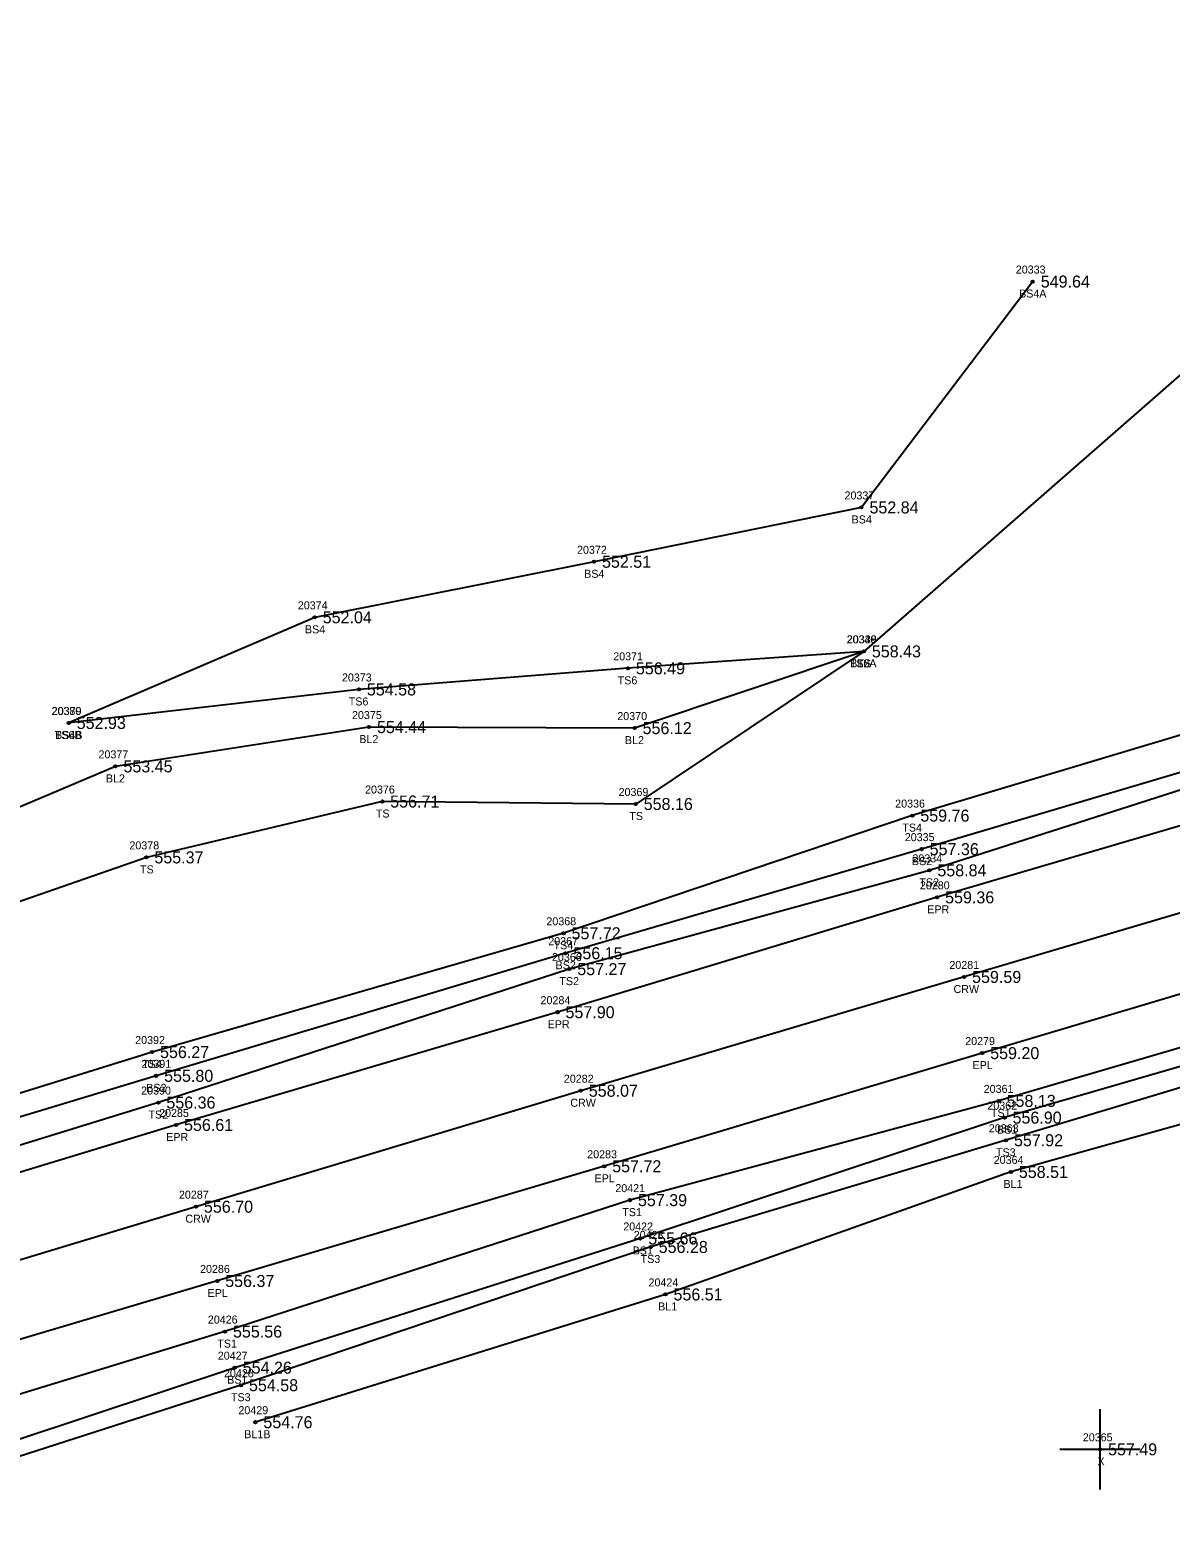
# Model space of a CAD drawing. Extents: x 1540443 to 1541844, y 887157 to 888162.
# Drawn here: x 1541511.2 to 1541653.6, y 887753.4 to 887940.4 of the extents above; entities that cross this region are included whole.
import ezdxf

# ---------------------------------------------------------------- set-up
doc = ezdxf.new("R2010")
doc.units = 0
for name, color, linetype in [('RD_DTM_BkLn1', 7, 'Continuous'), ('RD_DTM_BkLn2', 7, 'Continuous'), ('RD_DTM_BkLn_txCode', 7, 'Continuous'), ('RD_EX_Misc', 7, 'Continuous'), ('RD_EX_Misc_txCode', 7, 'Continuous'), ('RD_EX_Road', 7, 'Continuous'), ('RD_EX_Road_txCode', 7, 'Continuous'), ('RD_EX_TX_Misc_ELEV', 7, 'Continuous'), ('RD_EX_TX_Road_ELEV', 7, 'Continuous'), ('RD_HC_Survey_ELEV', 7, 'Continuous'), ('RD_HC_Survey_txCode', 7, 'Continuous'), ('RD_SMD_Locator', 7, 'Continuous')]:
    doc.layers.add(name, color=color, linetype=linetype)

msp = doc.modelspace()

# ---------------------------------------------------------------- linework, layer by layer
at = {"layer": 'RD_DTM_BkLn1'}
for points in [[(1541819.64, 887879.04), (1541771.84, 887865.01), (1541723.55, 887850.95), (1541675.82, 887836.26), (1541627.89, 887822.08), (1541580.01, 887807.87), (1541531.93, 887793.38), (1541484.13, 887778.91), (1541435.66, 887765.21), (1541388.1, 887751.04), (1541339.55, 887736.89), (1541291.46, 887723.08), (1541243.5, 887708.82), (1541195.27, 887694.78), (1541169.43, 887686.85)], [(1541615.37, 887862.76), (1541586.73, 887853.17), (1541553.55, 887853.3), (1541521.88, 887848.39), (1541484.86, 887832.7), (1541470.07, 887828.29), (1541413.13, 887806.68)], [(1541827.79, 887852.69), (1541775.52, 887840.39), (1541730.98, 887825.62), (1541683, 887811.47), (1541633.73, 887797.72), (1541590.59, 887782.42), (1541539.36, 887766.46)]]:
    msp.add_lwpolyline(points, dxfattribs=at)
at = {"layer": 'RD_DTM_BkLn2'}
for points in [[(1541705.44, 887940.39), (1541657.38, 887899.47), (1541615.37, 887862.76), (1541586.87, 887843.69), (1541555.2, 887844), (1541525.74, 887837.02), (1541487.41, 887823.68), (1541473.12, 887820.98), (1541413.13, 887806.68)], [(1541636.47, 887908.96), (1541615.07, 887880.74), (1541581.66, 887873.95), (1541546.77, 887867.01), (1541516.04, 887853.81)], [(1541814.01, 887898.31), (1541765.45, 887884.36), (1541753.72, 887881.26), (1541715.98, 887870.29), (1541668.78, 887856.47), (1541621.42, 887842.24), (1541577.85, 887827.54), (1541526.45, 887812.7), (1541478.33, 887797.72), (1541429.46, 887781.77)], [(1541814.49, 887896.02), (1541766.25, 887881.48), (1541716.95, 887866.26), (1541670.06, 887852.12), (1541622.59, 887838.05), (1541578.09, 887825.05), (1541526.96, 887809.73), (1541478.59, 887795.12), (1541429.46, 887781.77), (1541395.42, 887775.23), (1541380.33, 887789.16)], [(1541815.05, 887893.63), (1541767.74, 887877.82), (1541717.6, 887864.13), (1541670.44, 887850.43), (1541623.55, 887835.4), (1541578.57, 887823.06), (1541527.24, 887806.39), (1541479.99, 887791.81), (1541430.31, 887778.05), (1541393.69, 887768.38), (1541380.33, 887789.16)], [(1541824.97, 887864.95), (1541773.24, 887848.9), (1541728.33, 887834.59), (1541680.22, 887820.65), (1541632.2, 887806.6), (1541586.15, 887794.2), (1541535.56, 887777.78), (1541490.03, 887763.87), (1541442.11, 887749.28), (1541414.74, 887732.66), (1541394.55, 887728.51), (1541346.01, 887715.56), (1541298.68, 887704.05), (1541256.52, 887687.99), (1541253.67, 887682.12), (1541204.18, 887671.81), (1541185.24, 887668.7), (1541173.43, 887674.53)], [(1541826.01, 887862.16), (1541773.99, 887846.34), (1541729.05, 887832.97), (1541681.03, 887818.46), (1541632.94, 887804.51), (1541587.44, 887789.41), (1541536.78, 887773.27), (1541491.06, 887758.08), (1541445.99, 887740.14), (1541416.24, 887728.45), (1541395.49, 887723.75), (1541347.04, 887711.22), (1541300.85, 887696.02), (1541261.64, 887680.26), (1541255.59, 887675.42), (1541206.42, 887663.07), (1541174, 887652.79)], [(1541615.37, 887862.76), (1541585.89, 887860.64), (1541552.29, 887858), (1541516.04, 887853.81)], [(1541826.81, 887859.86), (1541774.16, 887844.66), (1541729.81, 887830.83), (1541681.55, 887816.28), (1541633.12, 887801.68), (1541588.74, 887788.35), (1541537.56, 887771.08), (1541491.43, 887756.24), (1541446.51, 887737.74), (1541416.24, 887728.45)]]:
    msp.add_lwpolyline(points, dxfattribs=at)
at = {"layer": 'RD_EX_Misc'}
for p, q in [((1541644.87, 887758.07), (1541644.87, 887768.07)), ((1541639.87, 887763.07), (1541649.87, 887763.07))]:
    msp.add_line(p, q, dxfattribs=at)
at = {"layer": 'RD_EX_Road'}
for points in [[(1541816.45, 887889.18), (1541769.26, 887875.17), (1541720.7, 887860.02), (1541673.15, 887846.35), (1541624.52, 887832.03), (1541577.1, 887817.68), (1541529.45, 887803.59), (1541481.09, 887788.89), (1541433.23, 887775.3), (1541384.84, 887760.56), (1541337.12, 887746.96), (1541288.35, 887732.65), (1541241.37, 887718.72), (1541192.23, 887703.89), (1541166.88, 887695.38)], [(1541823.08, 887870.08), (1541774.23, 887855.6), (1541726.64, 887841.16), (1541678.89, 887827.09), (1541630.15, 887812.57), (1541582.93, 887798.43), (1541534.59, 887784.1), (1541487.04, 887769.99), (1541438.64, 887755.66), (1541391.44, 887742.05), (1541342.36, 887727.48), (1541295.07, 887713.91), (1541246.74, 887699.66), (1541197.81, 887684.79), (1541172.48, 887676.63)]]:
    msp.add_lwpolyline(points, dxfattribs=at)
at = {"layer": 'RD_SMD_Locator'}
for centre in [(1541636.47, 887908.96), (1541615.07, 887880.74), (1541581.66, 887873.95), (1541546.77, 887867.01), (1541615.37, 887862.76), (1541615.37, 887862.76), (1541615.37, 887862.76), (1541585.89, 887860.64), (1541552.29, 887858), (1541516.04, 887853.81), (1541516.04, 887853.81), (1541553.55, 887853.3), (1541586.73, 887853.17), (1541521.88, 887848.39), (1541555.2, 887844), (1541586.87, 887843.69), (1541621.42, 887842.24), (1541622.59, 887838.05), (1541525.74, 887837.02), (1541623.55, 887835.4), (1541624.52, 887832.03), (1541577.85, 887827.54), (1541578.09, 887825.05), (1541578.57, 887823.06), (1541627.89, 887822.08), (1541577.1, 887817.68), (1541526.45, 887812.7), (1541630.15, 887812.57), (1541526.96, 887809.73), (1541580.01, 887807.87), (1541527.24, 887806.39), (1541632.2, 887806.6), (1541529.45, 887803.59), (1541632.94, 887804.51), (1541633.12, 887801.68), (1541582.93, 887798.43), (1541633.73, 887797.72), (1541586.15, 887794.2), (1541531.93, 887793.38), (1541587.44, 887789.41), (1541588.74, 887788.35), (1541534.59, 887784.1), (1541590.59, 887782.42), (1541535.56, 887777.78), (1541536.78, 887773.27), (1541537.56, 887771.08), (1541539.36, 887766.46), (1541644.87, 887763.07)]:
    msp.add_circle(centre, 0.15, dxfattribs=at)

# ---------------------------------------------------------------- texts
at = {"layer": 'RD_DTM_BkLn_txCode'}
for s, p in [('20333', (1541634.35, 887909.96)), ('BS4A', (1541634.76, 887906.96)), ('20337', (1541612.95, 887881.74)), ('BS4', (1541613.84, 887878.74)), ('20372', (1541579.54, 887874.95)), ('BS4', (1541580.43, 887871.95)), ('20374', (1541544.66, 887868.01)), ('BS4', (1541545.55, 887865.01)), ('20340', (1541613.21, 887863.76)), ('20338', (1541613.25, 887863.76)), ('20339', (1541613.25, 887863.76)), ('20371', (1541584.06, 887861.64)), ('TS6A', (1541613.61, 887860.76)), ('BL2A', (1541613.67, 887860.76)), ('TS', (1541614.57, 887860.76)), ('20373', (1541550.17, 887859)), ('TS6', (1541584.62, 887858.64)), ('TS6', (1541551.02, 887856)), ('20380', (1541513.89, 887854.81)), ('20379', (1541513.93, 887854.81)), ('20375', (1541551.43, 887854.3)), ('20370', (1541584.57, 887854.17)), ('TS6B', (1541514.3, 887851.81)), ('BS4B', (1541514.34, 887851.81)), ('BL2', (1541552.34, 887851.3)), ('BL2', (1541585.52, 887851.17)), ('20377', (1541519.76, 887849.39)), ('BL2', (1541520.68, 887846.39)), ('20376', (1541553.06, 887845)), ('20369', (1541584.73, 887844.69)), ('TS', (1541554.41, 887842)), ('20336', (1541619.28, 887843.24)), ('TS', (1541586.07, 887841.69)), ('TS4', (1541620.18, 887840.24)), ('20335', (1541620.48, 887839.05)), ('20378', (1541523.62, 887838.02)), ('20334', (1541621.43, 887836.4)), ('TS', (1541524.95, 887835.02)), ('BS2', (1541621.37, 887836.05)), ('TS2', (1541622.3, 887833.4)), ('20368', (1541575.71, 887828.54)), ('20367', (1541575.95, 887826.05)), ('TS4', (1541576.61, 887825.54)), ('20366', (1541576.41, 887824.06)), ('BS2', (1541576.86, 887823.05)), ('TS2', (1541577.33, 887821.06)), ('20392', (1541524.34, 887813.7)), ('20391', (1541525.13, 887810.73)), ('TS4', (1541525.21, 887810.7)), ('20390', (1541525.09, 887807.39)), ('BS2', (1541525.73, 887807.73)), ('20361', (1541630.34, 887807.6)), ('20362', (1541630.8, 887805.51)), ('TS1', (1541631.24, 887804.6)), ('TS2', (1541526, 887804.39)), ('20363', (1541630.98, 887802.68)), ('BS1', (1541632, 887802.51)), ('TS3', (1541631.88, 887799.68)), ('20364', (1541631.59, 887798.72)), ('20421', (1541584.32, 887795.2)), ('BL1', (1541632.81, 887795.72)), ('TS1', (1541585.19, 887792.2)), ('20422', (1541585.32, 887790.41)), ('20423', (1541586.62, 887789.35)), ('BS1', (1541586.49, 887787.41)), ('TS3', (1541587.49, 887786.35)), ('20424', (1541588.47, 887783.42)), ('BL1', (1541589.67, 887780.42)), ('20426', (1541533.42, 887778.78)), ('TS1', (1541534.6, 887775.78)), ('20427', (1541534.66, 887774.27)), ('20428', (1541535.44, 887772.08)), ('BS1', (1541535.83, 887771.27)), ('TS3', (1541536.31, 887769.08)), ('20429', (1541537.24, 887767.46)), ('BL1B', (1541537.97, 887764.46))]:
    msp.add_text(s, height=1, dxfattribs=at).set_placement(p)
at = {"layer": 'RD_EX_Misc_txCode'}
for s, p in [('20365', (1541642.72, 887764.07)), ('X', (1541644.55, 887761.07))]:
    msp.add_text(s, height=1, dxfattribs=at).set_placement(p)
at = {"layer": 'RD_EX_Road_txCode'}
for s, p in [('20280', (1541622.37, 887833.03)), ('EPR', (1541623.29, 887830.03)), ('20284', (1541574.98, 887818.68)), ('EPR', (1541575.87, 887815.68)), ('20279', (1541628.03, 887813.57)), ('EPL', (1541628.94, 887810.57)), ('20285', (1541527.33, 887804.59)), ('EPR', (1541528.22, 887801.59)), ('20283', (1541580.81, 887799.43)), ('EPL', (1541581.73, 887796.43)), ('20286', (1541532.45, 887785.1)), ('EPL', (1541533.39, 887782.1))]:
    msp.add_text(s, height=1, dxfattribs=at).set_placement(p)
at = {"layer": 'RD_EX_TX_Misc_ELEV'}
for s, p in [('549.64', (1541637.47, 887908.21)), ('552.84', (1541616.07, 887879.99)), ('552.51', (1541582.66, 887873.2)), ('552.04', (1541547.77, 887866.26)), ('558.43', (1541616.37, 887862.01)), ('558.43', (1541616.37, 887862.01)), ('558.43', (1541616.37, 887862.01)), ('556.49', (1541586.89, 887859.89)), ('554.58', (1541553.29, 887857.25)), ('552.93', (1541517.04, 887853.06)), ('552.93', (1541517.04, 887853.06)), ('554.44', (1541554.55, 887852.55)), ('556.12', (1541587.73, 887852.42)), ('553.45', (1541522.88, 887847.64)), ('556.71', (1541556.2, 887843.25)), ('558.16', (1541587.87, 887842.94)), ('559.76', (1541622.42, 887841.49)), ('555.37', (1541526.74, 887836.27)), ('557.36', (1541623.59, 887837.3)), ('558.84', (1541624.55, 887834.65)), ('557.72', (1541578.85, 887826.79)), ('556.15', (1541579.09, 887824.3)), ('557.27', (1541579.57, 887822.31)), ('556.27', (1541527.45, 887811.95)), ('555.80', (1541527.96, 887808.98)), ('558.13', (1541633.2, 887805.85)), ('556.36', (1541528.24, 887805.64)), ('556.90', (1541633.94, 887803.76)), ('557.92', (1541634.12, 887800.93)), ('558.51', (1541634.73, 887796.97)), ('557.39', (1541587.15, 887793.45)), ('555.66', (1541588.44, 887788.66)), ('556.28', (1541589.74, 887787.6)), ('556.51', (1541591.59, 887781.67)), ('555.56', (1541536.56, 887777.03)), ('554.26', (1541537.78, 887772.52)), ('554.58', (1541538.56, 887770.33)), ('554.76', (1541540.36, 887765.71)), ('557.49', (1541645.87, 887762.32))]:
    msp.add_text(s, height=1.5, dxfattribs=at).set_placement(p)
at = {"layer": 'RD_EX_TX_Road_ELEV'}
for s, p in [('559.36', (1541625.52, 887831.28)), ('557.90', (1541578.1, 887816.93)), ('559.20', (1541631.15, 887811.82)), ('556.61', (1541530.45, 887802.84)), ('557.72', (1541583.93, 887797.68)), ('556.37', (1541535.59, 887783.35))]:
    msp.add_text(s, height=1.5, dxfattribs=at).set_placement(p)
at = {"layer": 'RD_HC_Survey_ELEV'}
for s, p in [('559.59', (1541628.89, 887821.33)), ('558.07', (1541581.01, 887807.12)), ('556.70', (1541532.93, 887792.63))]:
    msp.add_text(s, height=1.5, dxfattribs=at).set_placement(p)
at = {"layer": 'RD_HC_Survey_txCode'}
for s, p in [('20281', (1541626.05, 887823.08)), ('CRW', (1541626.57, 887820.08)), ('20282', (1541577.89, 887808.87)), ('CRW', (1541578.7, 887805.87)), ('20287', (1541529.81, 887794.38)), ('CRW', (1541530.61, 887791.38))]:
    msp.add_text(s, height=1, dxfattribs=at).set_placement(p)

doc.saveas('drawing.dxf')
